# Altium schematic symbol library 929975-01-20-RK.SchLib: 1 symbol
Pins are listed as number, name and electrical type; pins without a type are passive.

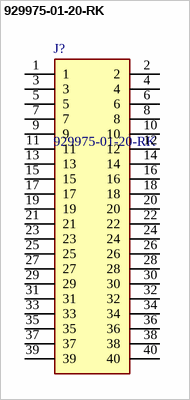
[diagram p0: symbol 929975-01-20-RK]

## 929975-01-20-RK
designator J?
Conn Socket Strip SKT 40 POS 2.54mm Solder ST Thru-Hole; Manufacturer_Name: 3M; Geometry.Height: 8.26mm
footprint RHDR40W76P254_2X20_5080X508X826P
pins: 1, 2, 3, 4, 5, 6, 7, 8, 9, 10, 11, 12, 13, 14, 15, 16, 17, 18, 19, 20, 21, 22, 23, 24, 25, 26, 27, 28, 29, 30, 31, 32, 33, 34, 35, 36, 37, 38, 39, 40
